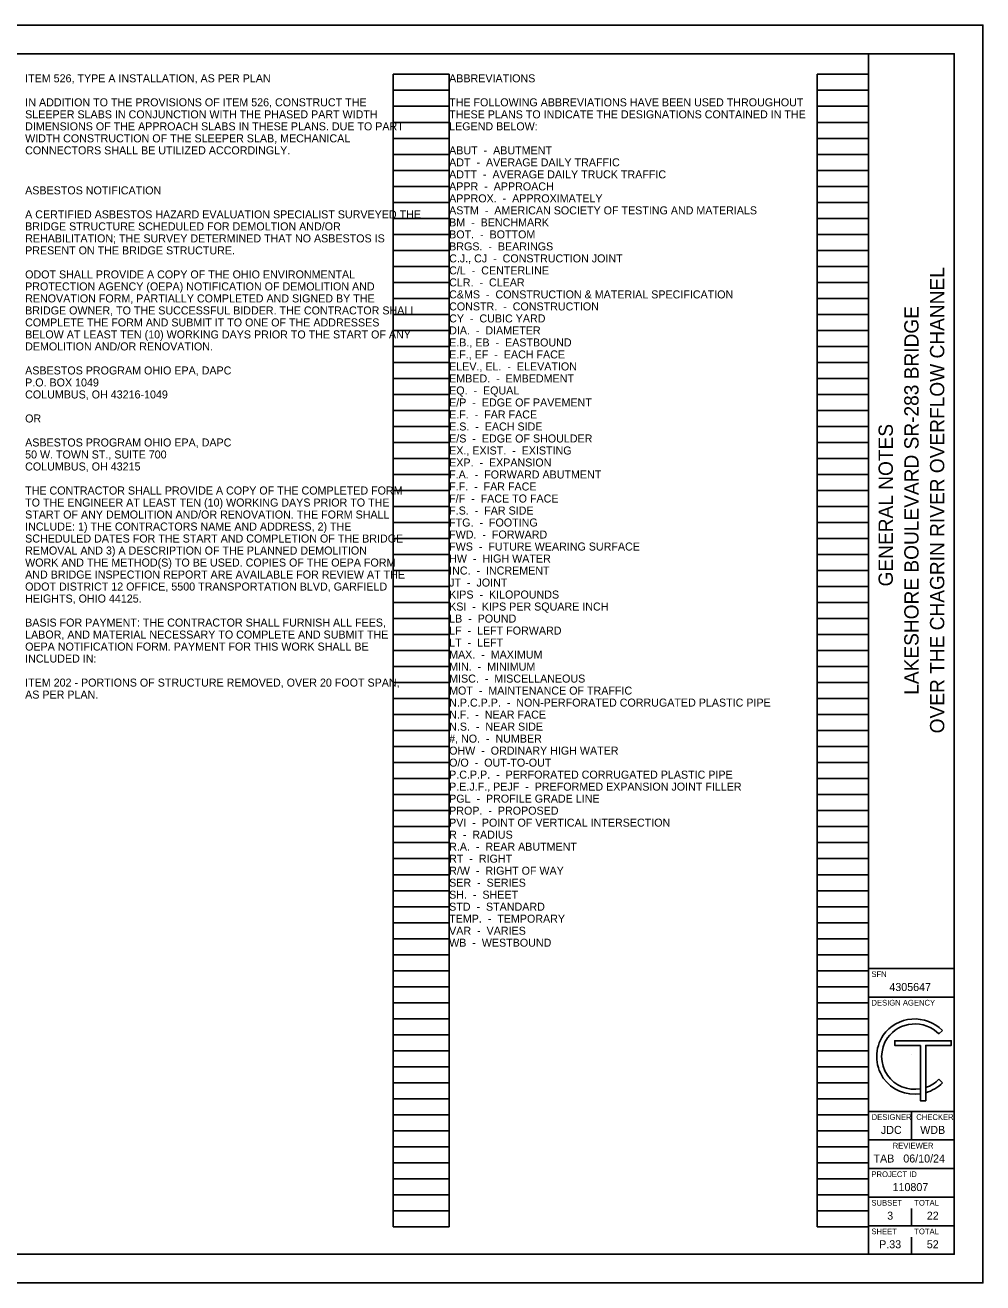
# Model space of a CAD drawing. Extents: x 0 to 34, y 0 to 22.
# Drawn here: x 17.24 to 34, y 0 to 22 of the extents above; entities that cross this region are included whole.
import ezdxf

# ---------------------------------------------------------------- set-up
doc = ezdxf.new("R2010")
doc.units = 0
for name, color, linetype in [('Default', 7, 'Continuous'), ('SH_Border', 7, 'Continuous'), ('SH_Cut_Line', 7, 'Continuous'), ('SH_Data', 7, 'Continuous'), ('SH_Text', 7, 'Continuous')]:
    doc.layers.add(name, color=color, linetype=linetype)

msp = doc.modelspace()

# ---------------------------------------------------------------- linework, layer by layer
at = {"layer": 'SH_Border'}
for p, q in [((32, 0.5), (32, 21.5)), ((32, 5.5), (33.5, 5.5)), ((32, 5), (33.5, 5)), ((32, 3), (33.5, 3)), ((32.75, 3), (32.75, 2.5)), ((32, 2.5), (33.5, 2.5)), ((32, 2), (33.5, 2)), ((32, 1.5), (33.5, 1.5)), ((32, 1), (33.5, 1))]:
    msp.add_line(p, q, dxfattribs=at)
msp.add_lwpolyline([(1.5, 21.5), (33.5, 21.5), (33.5, 0.5), (1.5, 0.5)], close=True, dxfattribs=at)
at = {"layer": 'SH_Cut_Line'}
msp.add_lwpolyline([(0, 0), (34, 0), (34, 22), (0, 22)], close=True, dxfattribs=at)
at = {"layer": 'SH_Data'}
for p, q in [((23.68, 0.98), (23.68, 21.14)), ((23.68, 21.14), (24.66, 21.14)), ((24.66, 0.98), (24.66, 21.14)), ((31.1, 0.98), (31.1, 21.14)), ((31.1, 21.14), (32, 21.14)), ((32, 0.98), (32, 21.14)), ((23.68, 20.86), (24.66, 20.86)), ((31.1, 20.86), (32, 20.86)), ((23.68, 20.58), (24.66, 20.58)), ((31.1, 20.58), (32, 20.58)), ((23.68, 20.3), (24.66, 20.3)), ((31.1, 20.3), (32, 20.3)), ((23.68, 20.02), (24.66, 20.02)), ((31.1, 20.02), (32, 20.02)), ((23.68, 19.74), (24.66, 19.74)), ((31.1, 19.74), (32, 19.74)), ((23.68, 19.46), (24.66, 19.46)), ((31.1, 19.46), (32, 19.46)), ((23.68, 19.18), (24.66, 19.18)), ((31.1, 19.18), (32, 19.18)), ((23.68, 18.9), (24.66, 18.9)), ((31.1, 18.9), (32, 18.9)), ((23.68, 18.62), (24.66, 18.62)), ((31.1, 18.62), (32, 18.62)), ((23.68, 18.34), (24.66, 18.34)), ((31.1, 18.34), (32, 18.34)), ((23.68, 18.06), (24.66, 18.06)), ((31.1, 18.06), (32, 18.06)), ((23.68, 17.78), (24.66, 17.78)), ((31.1, 17.78), (32, 17.78)), ((23.68, 17.5), (24.66, 17.5)), ((31.1, 17.5), (32, 17.5)), ((23.68, 17.22), (24.66, 17.22)), ((31.1, 17.22), (32, 17.22)), ((23.68, 16.94), (24.66, 16.94)), ((31.1, 16.94), (32, 16.94)), ((23.68, 16.66), (24.66, 16.66)), ((31.1, 16.66), (32, 16.66)), ((23.68, 16.38), (24.66, 16.38)), ((31.1, 16.38), (32, 16.38)), ((23.68, 16.1), (24.66, 16.1)), ((31.1, 16.1), (32, 16.1)), ((23.68, 15.82), (24.66, 15.82)), ((31.1, 15.82), (32, 15.82)), ((23.68, 15.54), (24.66, 15.54)), ((31.1, 15.54), (32, 15.54)), ((23.68, 15.26), (24.66, 15.26)), ((31.1, 15.26), (32, 15.26)), ((23.68, 14.98), (24.66, 14.98)), ((31.1, 14.98), (32, 14.98)), ((23.68, 14.7), (24.66, 14.7)), ((31.1, 14.7), (32, 14.7)), ((23.68, 14.42), (24.66, 14.42)), ((31.1, 14.42), (32, 14.42)), ((23.68, 14.14), (24.66, 14.14)), ((31.1, 14.14), (32, 14.14)), ((23.68, 13.86), (24.66, 13.86)), ((31.1, 13.86), (32, 13.86)), ((23.68, 13.58), (24.66, 13.58)), ((31.1, 13.58), (32, 13.58)), ((23.68, 13.3), (24.66, 13.3)), ((31.1, 13.3), (32, 13.3)), ((23.68, 13.02), (24.66, 13.02)), ((31.1, 13.02), (32, 13.02)), ((23.68, 12.74), (24.66, 12.74)), ((31.1, 12.74), (32, 12.74)), ((23.68, 12.46), (24.66, 12.46)), ((31.1, 12.46), (32, 12.46)), ((23.68, 12.18), (24.66, 12.18)), ((31.1, 12.18), (32, 12.18)), ((23.68, 11.9), (24.66, 11.9)), ((31.1, 11.9), (32, 11.9)), ((23.68, 11.62), (24.66, 11.62)), ((31.1, 11.62), (32, 11.62)), ((23.68, 11.34), (24.66, 11.34)), ((31.1, 11.34), (32, 11.34)), ((23.68, 11.06), (24.66, 11.06)), ((31.1, 11.06), (32, 11.06)), ((23.68, 10.78), (24.66, 10.78)), ((31.1, 10.78), (32, 10.78)), ((23.68, 10.5), (24.66, 10.5)), ((31.1, 10.5), (32, 10.5)), ((23.68, 10.22), (24.66, 10.22)), ((31.1, 10.22), (32, 10.22)), ((23.68, 9.94), (24.66, 9.94)), ((31.1, 9.94), (32, 9.94)), ((23.68, 9.66), (24.66, 9.66)), ((31.1, 9.66), (32, 9.66)), ((23.68, 9.38), (24.66, 9.38)), ((31.1, 9.38), (32, 9.38)), ((23.68, 9.1), (24.66, 9.1)), ((31.1, 9.1), (32, 9.1)), ((23.68, 8.82), (24.66, 8.82)), ((31.1, 8.82), (32, 8.82)), ((23.68, 8.54), (24.66, 8.54)), ((31.1, 8.54), (32, 8.54)), ((23.68, 8.26), (24.66, 8.26)), ((31.1, 8.26), (32, 8.26)), ((23.68, 7.98), (24.66, 7.98)), ((31.1, 7.98), (32, 7.98)), ((23.68, 7.7), (24.66, 7.7)), ((31.1, 7.7), (32, 7.7)), ((23.68, 7.42), (24.66, 7.42)), ((31.1, 7.42), (32, 7.42)), ((23.68, 7.14), (24.66, 7.14)), ((31.1, 7.14), (32, 7.14)), ((23.68, 6.86), (24.66, 6.86)), ((31.1, 6.86), (32, 6.86)), ((23.68, 6.58), (24.66, 6.58)), ((31.1, 6.58), (32, 6.58)), ((23.68, 6.3), (24.66, 6.3)), ((31.1, 6.3), (32, 6.3)), ((23.68, 6.02), (24.66, 6.02)), ((31.1, 6.02), (32, 6.02)), ((23.68, 5.74), (24.66, 5.74)), ((31.1, 5.74), (32, 5.74)), ((23.68, 5.46), (24.66, 5.46)), ((31.1, 5.46), (32, 5.46)), ((23.68, 5.18), (24.66, 5.18)), ((31.1, 5.18), (32, 5.18)), ((23.68, 4.9), (24.66, 4.9)), ((31.1, 4.9), (32, 4.9)), ((23.68, 4.62), (24.66, 4.62)), ((31.1, 4.62), (32, 4.62)), ((23.68, 4.34), (24.66, 4.34)), ((31.1, 4.34), (32, 4.34)), ((23.68, 4.06), (24.66, 4.06)), ((31.1, 4.06), (32, 4.06)), ((32.75, 4), (32.75, 4)), ((23.68, 3.78), (24.66, 3.78)), ((31.1, 3.78), (32, 3.78)), ((23.68, 3.5), (24.66, 3.5)), ((31.1, 3.5), (32, 3.5)), ((23.68, 3.22), (24.66, 3.22)), ((31.1, 3.22), (32, 3.22)), ((23.68, 2.94), (24.66, 2.94)), ((31.1, 2.94), (32, 2.94)), ((23.68, 2.66), (24.66, 2.66)), ((31.1, 2.66), (32, 2.66)), ((23.68, 2.38), (24.66, 2.38)), ((31.1, 2.38), (32, 2.38)), ((23.68, 2.1), (24.66, 2.1)), ((31.1, 2.1), (32, 2.1)), ((23.68, 1.82), (24.66, 1.82)), ((31.1, 1.82), (32, 1.82)), ((23.68, 1.54), (24.66, 1.54)), ((31.1, 1.54), (32, 1.54)), ((23.68, 1.26), (24.66, 1.26)), ((31.1, 1.26), (32, 1.26)), ((32.75, 1), (32.75, 1.3)), ((23.68, 0.98), (24.66, 0.98)), ((31.1, 0.98), (32, 0.98)), ((32.375, 0.675), (32.375, 0.675)), ((32.75, 0.5), (32.75, 0.8))]:
    msp.add_line(p, q, dxfattribs=at)
at = {"layer": 'SH_Text'}
for p, q in [((33.293, 4.415), (33.231, 4.354)), ((33.293, 4.415), (33.231, 4.354)), ((33.446, 4.234), (32.458, 4.234)), ((32.458, 4.234), (32.458, 4.152)), ((33.446, 4.152), (33.446, 4.234)), ((32.458, 4.152), (32.907, 4.152)), ((32.907, 4.152), (32.907, 3.186)), ((33, 3.186), (33, 4.152)), ((33, 4.152), (33.446, 4.152)), ((33.231, 3.562), (33.293, 3.5)), ((33.231, 3.562), (33.293, 3.5)), ((32.907, 3.394), (32.907, 3.306)), ((32.907, 3.394), (32.907, 3.306)), ((33, 3.326), (33, 3.417)), ((33, 3.326), (33, 3.417)), ((32.907, 3.186), (33, 3.186))]:
    msp.add_line(p, q, dxfattribs=at)
msp.add_lwpolyline([(32.907, 4.152), (32.907, 3.186), (33, 3.186), (33, 4.152), (33.446, 4.152), (33.446, 4.234), (32.458, 4.234), (32.458, 4.152)], close=True, dxfattribs=at)
for centre, radius, start, end in [((32.81, 3.936), 0.68, 44.7027, 144.3276), ((32.81, 3.936), 0.68, 44.7027, 144.3276), ((32.81, 3.936), 0.593, 44.7362, 144.1102), ((32.81, 3.936), 0.593, 44.7362, 144.1102), ((32.808, 3.958), 0.666, 145.7329, 214.2671), ((32.808, 3.958), 0.666, 145.7329, 214.2671), ((32.808, 3.958), 0.579, 145.7266, 214.2734), ((32.808, 3.958), 0.579, 145.7266, 214.2734), ((32.81, 3.979), 0.68, 215.6724, 278.2613), ((32.81, 3.979), 0.68, 215.6724, 278.2613), ((32.81, 3.979), 0.593, 215.8898, 279.4882), ((32.81, 3.979), 0.593, 215.8898, 279.4882), ((32.81, 3.979), 0.593, 288.6992, 315.2638), ((32.81, 3.979), 0.593, 288.6992, 315.2638), ((32.81, 3.979), 0.68, 286.2291, 315.2973), ((32.81, 3.979), 0.68, 286.2291, 315.2973)]:
    msp.add_arc(centre, radius, start, end, dxfattribs=at)

# ---------------------------------------------------------------- texts
at = {"layer": 'Default'}
for s, p in [('ITEM 526, TYPE A INSTALLATION, AS PER PLAN', (17.24, 21)), ('I', (17.24, 20.58)), ('N ADDITION TO THE PROVISIONS OF ITEM 526, CONSTRUCT THE ', (17.296, 20.58)), ('SLEEPER SLABS IN CONJUNCTION WITH THE PHASED PART WIDTH ', (17.24, 20.37)), ('DIMENSIONS OF THE APPROACH SLABS IN THESE PLANS. DUE TO PART ', (17.24, 20.16)), ('WIDTH CONSTRUCTION OF THE SLEEPER SLAB, MECHANICAL ', (17.24, 19.95)), ('CONNECTORS SHALL BE UTILIZED ACCORDINGLY.', (17.24, 19.74)), ('ASBESTOS NOTIFICATION', (17.24, 19.04)), ('A CERTIFIED ASBESTOS HAZARD EVALUATION SPECIALIST SURVEYED THE ', (17.24, 18.62)), ('BRIDGE STRUCTURE SCHEDULED FOR DEMOLTION AND/OR ', (17.24, 18.41)), ('REHABILITATION; THE SURVEY DETERMINED THAT NO ASBESTOS IS ', (17.24, 18.2)), ('PRESENT ON THE BRIDGE STRUCTURE.  ', (17.24, 17.99)), ('ODOT SHALL PROVIDE A COPY OF THE OHIO ENVIRONMENTAL ', (17.24, 17.57)), ('PROTECTION AGENCY (OEPA) NOTIFICATION OF DEMOLITION AND ', (17.24, 17.36)), ('RENOVATION FORM, PARTIALLY COMPLETED AND SIGNED BY THE ', (17.24, 17.15)), ('BRIDGE OWNER, TO THE SUCCESSFUL BIDDER. THE CONTRACTOR SHALL ', (17.24, 16.94)), ('COMPLETE THE FORM AND SUBMIT IT TO ONE OF THE ADDRESSES ', (17.24, 16.73)), ('BELOW AT LEAST TEN (10) WORKING DAYS PRIOR TO THE START OF ANY ', (17.24, 16.52)), ('DEMOLITION AND/OR RENOVATION. ', (17.24, 16.31)), ('ASBESTOS PROGRAM OHIO EPA, DAPC ', (17.24, 15.89)), ('P.O. BOX 1049 ', (17.24, 15.68)), ('COLUMBUS, OH 43216-1049 ', (17.24, 15.47)), ('OR ', (17.24, 15.05)), ('ASBESTOS PROGRAM OHIO EPA, DAPC ', (17.24, 14.63)), ('50 W. TOWN ST., SUITE 700 ', (17.24, 14.42)), ('COLUMBUS, OH 43215 ', (17.24, 14.21)), ('THE CONTRACTOR SHALL PROVIDE A COPY OF THE COMPLETED FORM ', (17.24, 13.79)), ('TO THE ENGINEER AT LEAST TEN (10) WORKING DAYS PRIOR TO THE ', (17.24, 13.58)), ('START OF ANY DEMOLITION AND/OR RENOVATION. THE FORM SHALL ', (17.24, 13.37)), ('INCLUDE: 1) THE CONTRACTORS NAME AND ADDRESS, 2) THE ', (17.24, 13.16)), ('SCHEDULED DATES FOR THE START AND COMPLETION OF THE BRIDGE ', (17.24, 12.95)), ('REMOVAL AND 3) A DESCRIPTION OF THE PLANNED DEMOLITION ', (17.24, 12.74)), ('WORK AND THE METHOD(S) TO BE USED. COPIES OF THE OEPA FORM ', (17.24, 12.53)), ('AND BRIDGE INSPECTION REPORT ARE AVAILABLE FOR REVIEW AT THE ', (17.24, 12.32)), ('ODOT DISTRICT 12 OFFICE, 5500 TRANSPORTATION BLVD, GARFIELD ', (17.24, 12.11)), ('HEIGHTS, OHIO 44125. ', (17.24, 11.9)), ('BASIS FOR PAYMENT: THE CONTRACTOR SHALL FURNISH ALL FEES, ', (17.24, 11.48)), ('LABOR, AND MATERIAL NECESSARY TO COMPLETE AND SUBMIT THE ', (17.24, 11.27)), ('OEPA NOTIFICATION FORM. PAYMENT FOR THIS WORK SHALL BE ', (17.24, 11.06)), ('INCLUDED IN:', (17.24, 10.85)), ('ITEM 202 - PORTIONS OF STRUCTURE REMOVED, OVER 20 FOOT SPAN, ', (17.24, 10.43)), ('AS PER PLAN.', (17.24, 10.22))]:
    msp.add_text(s, height=0.14, dxfattribs=at).set_placement(p)
at = {"layer": 'SH_Data'}
for s, p in [('OVER THE CHAGRIN RIVER OVERFLOW CHANNEL', (33.325, 9.612)), ('LAKESHORE BOULEVARD SR-283 BRIDGE', (32.875, 10.287)), ('GENERAL NOTES', (32.425, 12.182))]:
    msp.add_text(s, height=0.25, rotation=90, dxfattribs=at).set_placement(p)
for s, height, p in [('SFN', 0.1, (32.05, 5.35)), ('4305647', 0.14, (32.364, 5.105)), ('DESIGN AGENCY', 0.1, (32.05, 4.85)), ('DESIGNER', 0.1, (32.054, 2.85)), ('CHECKER', 0.1, (32.835, 2.85)), ('JDC', 0.14, (32.216, 2.605)), ('WDB', 0.14, (32.904, 2.605)), ('REVIEWER', 0.1, (32.422, 2.35)), ('TAB', 0.14, (32.086, 2.105)), ('06/10/24', 0.14, (32.608, 2.105)), ('PROJECT ID', 0.1, (32.05, 1.85)), ('110807', 0.14, (32.42, 1.605)), ('SUBSET', 0.1, (32.05, 1.35)), ('TOTAL', 0.1, (32.8, 1.35)), ('3', 0.14, (32.326, 1.105)), ('22', 0.14, (33.019, 1.105)), ('SHEET', 0.1, (32.05, 0.85)), ('TOTAL', 0.1, (32.8, 0.85)), ('P.33', 0.14, (32.185, 0.605)), ('52', 0.14, (33.019, 0.605))]:
    msp.add_text(s, height=height, dxfattribs=at).set_placement(p)
at = {"layer": 'SH_Text'}
for s, p in [('ABBREVIATIONS', (24.66, 21)), ('THE FOLLOWING ABBREVIATIONS HAVE BEEN USED THROUGHOUT', (24.66, 20.58)), ('THESE PLANS TO INDICATE THE DESIGNATIONS CONTAINED IN THE', (24.66, 20.37)), ('LEGEND BELOW:', (24.66, 20.16)), ('ABUT  -  ABUTMENT', (24.66, 19.74)), ('ADT  -  AVERAGE DAILY TRAFFIC', (24.66, 19.53)), ('ADTT  -  AVERAGE DAILY TRUCK TRAFFIC', (24.66, 19.32)), ('APPR  -  APPROACH', (24.66, 19.11)), ('APPROX.  -  APPROXIMATELY', (24.66, 18.9)), ('ASTM  -  AMERICAN SOCIETY OF TESTING AND MATERIALS', (24.66, 18.69)), ('BM  -  BENCHMARK', (24.66, 18.48)), ('BOT.  -  BOTTOM', (24.66, 18.27)), ('BRGS.  -  BEARINGS', (24.66, 18.06)), ('C.J., CJ  -  CONSTRUCTION JOINT', (24.66, 17.85)), ('C/L  -  CENTERLINE', (24.66, 17.64)), ('CLR.  -  CLEAR', (24.66, 17.43)), ('C&MS  -  CONSTRUCTION & MATERIAL SPECIFICATION', (24.66, 17.22)), ('CONSTR.  -  CONSTRUCTION', (24.66, 17.01)), ('CY  -  CUBIC YARD', (24.66, 16.8)), ('DIA.  -  DIAMETER', (24.66, 16.59)), ('E.B., EB  -  EASTBOUND', (24.66, 16.38)), ('E.F., EF  -  EACH FACE', (24.66, 16.17)), ('ELEV., EL.  -  ELEVATION', (24.66, 15.96)), ('EMBED.  -  EMBEDMENT', (24.66, 15.75)), ('EQ.  -  EQUAL', (24.66, 15.54)), ('E/P  -  EDGE OF PAVEMENT', (24.66, 15.33)), ('E.F.  -  FAR FACE', (24.66, 15.12)), ('E.S.  -  EACH SIDE', (24.66, 14.91)), ('E/S  -  EDGE OF SHOULDER', (24.66, 14.7)), ('EX., EXIST.  -  EXISTING', (24.66, 14.49)), ('EXP.  -  EXPANSION', (24.66, 14.28)), ('F.A.  -  FORWARD ABUTMENT', (24.66, 14.07)), ('F.F.  -  FAR FACE', (24.66, 13.86)), ('F/F  -  FACE TO FACE', (24.66, 13.65)), ('F.S.  -  FAR SIDE', (24.66, 13.44)), ('FTG.  -  FOOTING', (24.66, 13.23)), ('FWD.  -  FORWARD', (24.66, 13.02)), ('FWS  -  FUTURE WEARING SURFACE', (24.66, 12.81)), ('HW  -  HIGH WATER', (24.66, 12.6)), ('JT  -  JOINT', (24.66, 12.18)), ('INC.  -  INCREMENT', (24.66, 12.39)), ('KIPS  -  KILOPOUNDS', (24.66, 11.97)), ('KSI  -  KIPS PER SQUARE INCH', (24.66, 11.76)), ('LB  -  POUND', (24.66, 11.55)), ('LF  -  LEFT FORWARD', (24.66, 11.34)), ('LT  -  LEFT', (24.66, 11.13)), ('MAX.  -  MAXIMUM', (24.66, 10.92)), ('MIN.  -  MINIMUM', (24.66, 10.71)), ('MISC.  -  MISCELLANEOUS', (24.66, 10.5)), ('MOT  -  MAINTENANCE OF TRAFFIC', (24.66, 10.29)), ('N.P.C.P.P.  -  NON-PERFORATED CORRUGATED PLASTIC PIPE', (24.66, 10.08)), ('N.F.  -  NEAR FACE', (24.66, 9.87)), ('N.S.  -  NEAR SIDE', (24.66, 9.66)), ('#, NO.  -  NUMBER', (24.66, 9.45)), ('OHW  -  ORDINARY HIGH WATER', (24.66, 9.24)), ('O/O  -  OUT-TO-OUT', (24.66, 9.03)), ('P.C.P.P.  -  PERFORATED CORRUGATED PLASTIC PIPE', (24.66, 8.82)), ('P.E.J.F., PEJF  -  PREFORMED EXPANSION JOINT FILLER', (24.66, 8.61)), ('PGL  -  PROFILE GRADE LINE', (24.66, 8.4)), ('PROP.  -  PROPOSED', (24.66, 8.19)), ('PVI  -  POINT OF VERTICAL INTERSECTION', (24.66, 7.98)), ('R  -  RADIUS', (24.66, 7.77)), ('R.A.  -  REAR ABUTMENT', (24.66, 7.56)), ('RT  -  RIGHT', (24.66, 7.35)), ('R/W  -  RIGHT OF WAY', (24.66, 7.14)), ('SER  -  SERIES', (24.66, 6.93)), ('SH.  -  SHEET', (24.66, 6.72)), ('STD  -  STANDARD', (24.66, 6.51)), ('TEMP.  -  TEMPORARY', (24.66, 6.3)), ('VAR  -  VARIES', (24.66, 6.09)), ('WB  -  WESTBOUND', (24.66, 5.88))]:
    msp.add_text(s, height=0.14, dxfattribs=at).set_placement(p)

doc.saveas('drawing.dxf')
